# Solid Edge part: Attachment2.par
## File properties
Username: m_hel
Author: m_hel
Template: Iso Metric Part.par
Last saved by: m_hel
Revision: 5
Application: Solid Edge
Accuracy: 0,990
Material: Chrome
Face Style: Chrome
Fill Style: Normal
Virtual Style: Normal
Grouping: Uncategorized
LibraryName: Custom Materials
Coef. of Thermal Exp: 0.0
Thermal Conductivity: 0.0
Specific Heat: 0.0
Modulus of Elasticity: 0.0
Poisson's Ratio: 0.0
Yield Stress: 0.0
Ultimate Stress: 0.0
Elongation: 0.0
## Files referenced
..\..\Redfisher18.asm
G:\OneDriveTemp\OneDrive\Dokumendid\TLÜ tööd\3D Modelleerimine\3d modelling\veesõiduk\Engine\Attachment.par
iduk\Engine\Attachment.par
iduk\Redfisher18.asm
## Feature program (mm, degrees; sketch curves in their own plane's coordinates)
sketch for "unnamed Protrusion 1" plane through (0, 0, 0) normal (0, 0, 1) x-axis (1, 0, 0)
  line (-125, -60) -> (-50, -60)
  line (-125, 30) -> (-125, -60)
  line (-125, 30) -> (125, 30)
  line (125, -60) -> (125, 30)
  line (50, -60) -> (125, -60)
extrude "unnamed Protrusion 1" add finite 60 symmetric
sketch for "unnamed Protrusion 2" plane through (-125, -15, 0) normal (-1, 0, 0) x-axis (0, -1, 0)
  circle centre (-45, 0) radius 30
extrude "unnamed Protrusion 2" add to key point along -normal
sketch for "unnamed Cutout 1" #1 plane through (0, -40, 30) normal (0, 0, 1) x-axis (0, -1, 0)
  line (-40, -125) -> (-100, -125)
  line (-100, -125) -> (-100, -82.5)
  line (-40, -82.5) -> (-100, -82.5)
  line (-40, -82.5) -> (-40, -125)
sketch for "unnamed Cutout 1" #2 plane through (0, -40, 30) normal (0, 0, 1) x-axis (0, -1, 0)
  line (-100, -42.5) -> (-100, 42.5)
  line (-40, 42.5) -> (-100, 42.5)
  line (-40, 42.5) -> (-40, -42.5)
  line (-40, -42.5) -> (-100, -42.5)
sketch for "unnamed Cutout 1" #3 plane through (0, -40, 30) normal (0, 0, 1) x-axis (0, -1, 0)
  line (-100, 125) -> (-40, 125)
  line (-40, 125) -> (-40, 82.5)
  line (-40, 82.5) -> (-100, 82.5)
  line (-100, 82.5) -> (-100, 125)
extrude "unnamed Cutout 1" cut through along -normal
sketch for "unnamed Cutout 2" plane through (0, -40, 30) normal (0, 0, 1) x-axis (0, -1, 0)
  circle centre (20, 0) radius 25
extrude "unnamed Cutout 2" cut through along -normal
fillet "Round_1" radius 5
chamfer "Chamfer_1" setback 30
sketch for "unnamed Cutout 3" plane through (-125, -15, 0) normal (-1, 0, 0) x-axis (0, -1, 0)
  circle centre (-45, 0) radius 15
extrude "unnamed Cutout 3" cut through along -normal
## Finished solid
Body 1: solid body, 35 faces, 88 edges, 52 vertices.
  Faces by surface: plane 15, cylinder 14, torus 6
  Edges by curve: line 50, circle 38
Bounding box of the edges (mm; curved faces can reach further): 250.000 x 170.000 x 60.000, from (-125, -110, -30) to (125, 60, 30).
Cylindrical faces by radius (mm): R5 x8, R15 x2, R25 x1, R30 x2, R50 x1
Toroidal faces (ring radius, tube radius in mm): R25 r5 x4, R45 r5 x2
Planar faces by outward normal: +x 3, +y 3, +z 1, -x 3, -y 2, -z 1, oblique 2
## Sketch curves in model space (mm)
line (125, -60, 0) -> (125, 30, 0)
line (-125, 30, 0) -> (125, 30, 0)
line (-125, 30, 0) -> (-125, -60, 0)
line (-125, -60, 0) -> (-50, -60, 0)
arc centre (0, -60, 0) radius 50 from (50, -60, 0) through (-1.4817, -109.978, 0) to (-50, -60, 0)
line (50, -60, 0) -> (125, -60, 0)
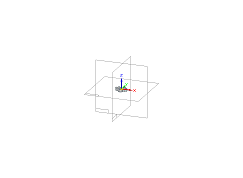
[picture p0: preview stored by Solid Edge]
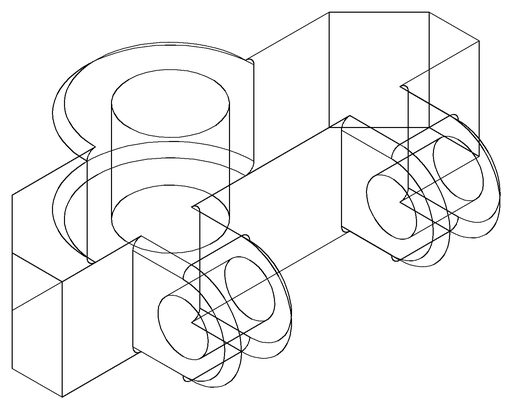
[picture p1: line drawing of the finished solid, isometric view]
